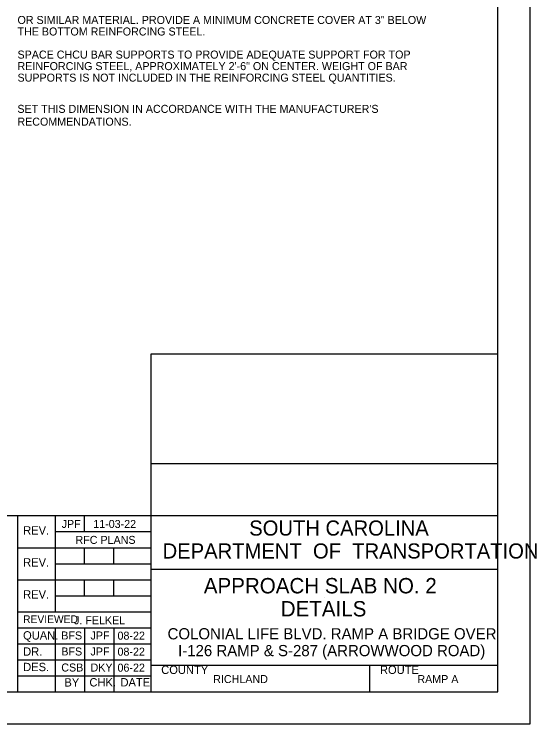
# Model space of a CAD drawing. Extents: x 2799.7 to 2896, y 515.2 to 573.9.
# Drawn here: x 2874.21 to 2895.98, y 515.22 to 544.77 of the extents above; entities that cross this region are included whole.
import ezdxf

# ---------------------------------------------------------------- set-up
doc = ezdxf.new("R2010")
doc.units = 0
for name, color, linetype in [('BR_BORDER LINES', 7, 'Continuous'), ('BR_TEXT', 7, 'Continuous'), ('Level 31', 7, 'Continuous')]:
    doc.layers.add(name, color=color, linetype=linetype)

msp = doc.modelspace()

# ---------------------------------------------------------------- linework, layer by layer
at = {"layer": 'BR_BORDER LINES'}
for p, q in [((2894.359, 516.556), (2894.359, 572.556)), ((2879.914, 516.556), (2879.914, 530.627)), ((2879.914, 530.627), (2894.359, 530.627)), ((2879.914, 526.054), (2894.359, 526.054)), ((2860.05, 523.89), (2874.358, 523.89)), ((2874.358, 516.556), (2874.358, 523.89)), ((2874.358, 523.89), (2894.359, 523.89)), ((2875.913, 523.89), (2875.913, 519.889)), ((2877.136, 523.223), (2877.136, 523.89)), ((2875.913, 523.223), (2879.914, 523.223)), ((2874.358, 522.556), (2879.914, 522.556)), ((2877.136, 521.889), (2877.136, 522.556)), ((2878.358, 521.889), (2878.358, 522.556)), ((2875.913, 521.889), (2879.914, 521.889)), ((2879.914, 521.667), (2879.914, 521.667)), ((2879.914, 521.667), (2894.359, 521.667)), ((2874.358, 521.223), (2879.914, 521.223)), ((2877.136, 520.556), (2877.136, 521.223)), ((2878.358, 520.556), (2878.358, 521.223)), ((2875.913, 520.556), (2879.914, 520.556)), ((2874.358, 519.889), (2879.914, 519.889)), ((2874.358, 519.223), (2879.914, 519.223)), ((2875.913, 519.223), (2875.913, 516.556)), ((2877.136, 519.223), (2877.136, 516.556)), ((2878.358, 519.223), (2878.358, 516.556)), ((2874.358, 518.556), (2879.914, 518.556)), ((2874.358, 517.889), (2879.914, 517.889)), ((2879.914, 517.667), (2894.359, 517.667)), ((2880.174, 517.667), (2894.359, 517.667)), ((2889.025, 516.556), (2889.025, 517.667)), ((2874.358, 517.223), (2879.914, 517.223)), ((2804.582, 516.556), (2894.359, 516.556))]:
    msp.add_line(p, q, dxfattribs=at)
at = {"layer": 'Level 31'}
msp.add_line((2887.137, 520.493), (2887.137, 520.493), dxfattribs=at)
msp.add_lwpolyline([(2799.693, 573.89), (2799.693, 515.223), (2895.694, 515.223), (2895.694, 573.89)], dxfattribs=at)

# ---------------------------------------------------------------- texts
at = {"layer": 'BR_TEXT'}
for s, p in [('OR SIMILAR MATERIAL. PROVIDE A MINIMUM CONCRETE COVER AT 3" BELOW ', (2874.348, 544.361)), ('THE BOTTOM REINFORCING STEEL. ', (2874.348, 543.881)), ('SPACE CHCU BAR SUPPORTS TO PROVIDE ADEQUATE SUPPORT FOR TOP ', (2874.348, 542.92)), ('REINFORCING STEEL, APPROXIMATELY 2\'-6" ON CENTER. WEIGHT OF BAR ', (2874.348, 542.44)), ('SUPPORTS IS NOT INCLUDED IN THE REINFORCING STEEL QUANTITIES. ', (2874.348, 541.96))]:
    msp.add_text(s, height=0.33333, rotation=360, dxfattribs=at).set_placement(p)
for s, height, p in [("SET THIS DIMENSION IN ACCORDANCE WITH THE MANUFACTURER'S", 0.33332, (2874.343, 540.66)), ('RECOMMENDATIONS.', 0.33332, (2874.343, 540.127)), ('JPF', 0.3333, (2876.186, 523.377)), ('11-03-22', 0.3333, (2877.503, 523.377)), ('SOUTH CAROLINA', 0.629, (2883.999, 523.059)), ('REV.', 0.3467, (2874.584, 523.104)), ('RFC PLANS', 0.3333, (2876.763, 522.713)), ('DEPARTMENT  OF  TRANSPORTATION', 0.629, (2880.392, 522.105)), ('REV.', 0.3467, (2874.584, 521.771)), ('APPROACH SLAB NO. 2', 0.64001, (2882.107, 520.653)), ('REV.', 0.3467, (2874.584, 520.437)), ('DETAILS', 0.64, (2885.312, 519.693)), ('REVIEWED', 0.32, (2874.582, 519.419)), ('J. FELKEL', 0.3333, (2876.702, 519.368)), ('COLONIAL LIFE BLVD. RAMP A BRIDGE OVER', 0.46667, (2880.598, 518.738)), ('QUAN.', 0.3467, (2874.58, 518.73)), ('BFS', 0.3333, (2876.171, 518.733)), ('JPF', 0.3333, (2877.39, 518.733)), ('08-22', 0.3333, (2878.513, 518.727)), ('I-126 RAMP & S-287 (ARROWWOOD ROAD)', 0.46667, (2881.036, 518.038)), ('DR.', 0.3467, (2874.581, 518.059)), ('BFS', 0.3333, (2876.173, 518.067)), ('JPF', 0.3333, (2877.388, 518.067)), ('08-22', 0.3333, (2878.513, 518.06)), ('DES.', 0.3467, (2874.584, 517.415)), ('CSB', 0.3333, (2876.171, 517.4)), ('DKY', 0.3333, (2877.39, 517.4)), ('06-22', 0.3333, (2878.513, 517.394)), ('COUNTY', 0.3467, (2880.333, 517.298)), ('ROUTE', 0.3467, (2889.445, 517.298)), ('BY', 0.3467, (2876.301, 516.774)), ('CHK.', 0.3467, (2877.343, 516.778)), ('DATE', 0.3467, (2878.637, 516.778)), ('RICHLAND', 0.3333, (2882.499, 516.919)), ('RAMP A', 0.3333, (2891.003, 516.919))]:
    msp.add_text(s, height=height, dxfattribs=at).set_placement(p)

doc.saveas('drawing.dxf')
